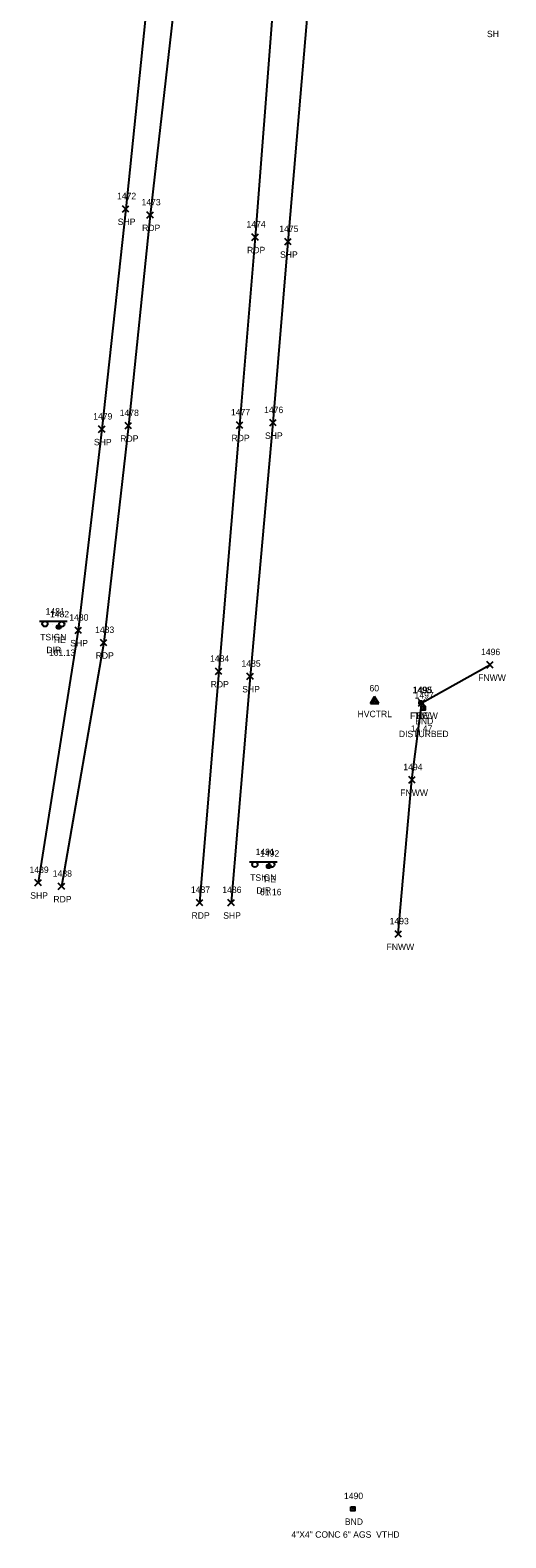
# Model space of a CAD drawing. Extents: x 1443960 to 1446865, y 610387 to 616706.
# Drawn here: x 1446513 to 1446660.7, y 610386.8 to 610855.3 of the extents above; entities that cross this region are included whole.
import ezdxf

# ---------------------------------------------------------------- set-up
doc = ezdxf.new("R2010")
doc.units = 0
for name, color, linetype in [('C_A', 7, 'Continuous'), ('C_C', 7, 'Continuous'), ('C_I', 7, 'Continuous'), ('CBP', 7, 'Continuous'), ('CPSM', 7, 'Continuous'), ('L_A', 7, 'Continuous'), ('L_I', 7, 'Continuous'), ('L_TIC', 7, 'Continuous'), ('LFNC', 7, 'Continuous'), ('M_A', 7, 'Continuous'), ('M_C', 7, 'Continuous'), ('M_I', 7, 'Continuous'), ('MHBP', 7, 'Continuous'), ('P_A', 7, 'Continuous'), ('P_I', 7, 'Continuous'), ('P_TIC', 7, 'Continuous'), ('PET', 7, 'Continuous'), ('PSP', 7, 'Continuous'), ('S_A', 7, 'Continuous'), ('S_C', 7, 'Continuous'), ('S_I', 7, 'Continuous'), ('SSGN', 7, 'Continuous')]:
    doc.layers.add(name, color=color, linetype=linetype)

msp = doc.modelspace()

# ---------------------------------------------------------------- linework, layer by layer
at = {"layer": 'CBP'}
for centre, radius in [((1446521.81, 610669.87), 0.625), ((1446521.81, 610669.87), 0.0833), ((1446634.4, 610646.3), 0.625), ((1446634.4, 610646.3), 0.0833), ((1446587.07, 610595.51), 0.625), ((1446587.07, 610595.51), 0.0833)]:
    msp.add_circle(centre, radius, dxfattribs=at)
at = {"layer": 'CPSM'}
for p, q in [((1446618.73, 610646.12), (1446619.98, 610648.28)), ((1446618.73, 610646.12), (1446619.98, 610646.84)), ((1446618.73, 610646.12), (1446621.23, 610646.12)), ((1446621.23, 610646.12), (1446619.98, 610648.28)), ((1446619.98, 610646.84), (1446619.98, 610648.28)), ((1446619.98, 610646.84), (1446619.98, 610646.84)), ((1446619.98, 610646.84), (1446621.23, 610646.12))]:
    msp.add_line(p, q, dxfattribs=at)
at = {"layer": 'L_TIC'}
for points in [[(1446654.78, 610657.12), (1446656.78, 610659.12)], [(1446656.78, 610657.12), (1446654.78, 610659.12)], [(1446633.64, 610645.31), (1446635.64, 610647.31)], [(1446635.64, 610645.31), (1446633.64, 610647.31)], [(1446630.58, 610621.37), (1446632.58, 610623.37)], [(1446632.58, 610621.37), (1446630.58, 610623.37)], [(1446626.32, 610573.48), (1446628.32, 610575.48)], [(1446628.32, 610573.48), (1446626.32, 610575.48)]]:
    msp.add_lwpolyline(points, dxfattribs=at)
at = {"layer": 'LFNC'}
msp.add_lwpolyline([(1446627.32, 610574.48), (1446631.58, 610622.37), (1446634.64, 610646.31), (1446655.78, 610658.12)], dxfattribs=at)
at = {"layer": 'MHBP'}
for points in [[(1446634.44, 610645.26), (1446635.69, 610645.26), (1446635.69, 610644.01), (1446634.44, 610644.01)], [(1446612.61, 610396.47), (1446613.86, 610396.47), (1446613.86, 610395.22), (1446612.61, 610395.22)]]:
    msp.add_lwpolyline(points, close=True, dxfattribs=at)
for centre in [(1446635.07, 610644.64), (1446613.24, 610395.85)]:
    msp.add_circle(centre, 0.0833, dxfattribs=at)
at = {"layer": 'P_TIC'}
for points in [[(1446541.65, 610798.79), (1446543.65, 610800.79)], [(1446543.65, 610798.79), (1446541.65, 610800.79)], [(1446549.26, 610796.89), (1446551.26, 610798.89)], [(1446551.26, 610796.89), (1446549.26, 610798.89)], [(1446581.86, 610790.01), (1446583.86, 610792.01)], [(1446583.86, 610790.01), (1446581.86, 610792.01)], [(1446592.05, 610788.59), (1446594.05, 610790.59)], [(1446594.05, 610788.59), (1446592.05, 610790.59)], [(1446587.39, 610732.33), (1446589.39, 610734.33)], [(1446589.39, 610732.33), (1446587.39, 610734.33)], [(1446534.25, 610730.33), (1446536.25, 610732.33)], [(1446536.25, 610730.33), (1446534.25, 610732.33)], [(1446542.48, 610731.42), (1446544.48, 610733.42)], [(1446544.48, 610731.42), (1446542.48, 610733.42)], [(1446577.03, 610731.6), (1446579.03, 610733.6)], [(1446579.03, 610731.6), (1446577.03, 610733.6)], [(1446526.9, 610667.85), (1446528.9, 610669.85)], [(1446528.9, 610667.85), (1446526.9, 610669.85)], [(1446534.83, 610664.01), (1446536.83, 610666.01)], [(1446536.83, 610664.01), (1446534.83, 610666.01)], [(1446570.55, 610655.07), (1446572.55, 610657.07)], [(1446572.55, 610655.07), (1446570.55, 610657.07)], [(1446580.3, 610653.53), (1446582.3, 610655.53)], [(1446582.3, 610653.53), (1446580.3, 610655.53)], [(1446514.47, 610589.43), (1446516.47, 610591.43)], [(1446516.47, 610589.43), (1446514.47, 610591.43)], [(1446521.7, 610588.27), (1446523.7, 610590.27)], [(1446523.7, 610588.27), (1446521.7, 610590.27)], [(1446564.6, 610583.23), (1446566.6, 610585.23)], [(1446566.6, 610583.23), (1446564.6, 610585.23)], [(1446574.41, 610583.21), (1446576.41, 610585.21)], [(1446576.41, 610583.21), (1446574.41, 610585.21)]]:
    msp.add_lwpolyline(points, dxfattribs=at)
at = {"layer": 'PET'}
for points in [[(1446586.96, 611148.93), (1446585.91, 611138.65), (1446581.07, 611085.82), (1446577.8, 611049), (1446573.67, 611008.09), (1446567.43, 610950.16), (1446562.94, 610911.75), (1446557.73, 610863.22), (1446550.26, 610797.89), (1446543.48, 610732.42), (1446535.83, 610665.01), (1446522.7, 610589.27)], [(1446610.71, 611136.75), (1446609.78, 611124.94), (1446606.08, 611083.4), (1446602.84, 611045.86), (1446594.91, 610952.22), (1446591.25, 610905.91), (1446588.27, 610860.89), (1446582.86, 610791.01), (1446578.03, 610732.6), (1446571.55, 610656.07), (1446565.6, 610584.23)]]:
    msp.add_lwpolyline(points, dxfattribs=at)
at = {"layer": 'PSP'}
for points in [[(1446576.92, 611154.08), (1446576.88, 611153.48), (1446576.38, 611146.03), (1446571.14, 611086.78), (1446567.69, 611049.79), (1446563.76, 611009.43), (1446561.38, 610989.08), (1446557.86, 610953.83), (1446553.98, 610913.79), (1446549.11, 610862.52), (1446542.65, 610799.79), (1446535.25, 610731.33), (1446527.9, 610668.85), (1446515.47, 610590.43)], [(1446619.04, 611132.42), (1446618.93, 611131.58), (1446619.27, 611123.52), (1446616.01, 611082.04), (1446613.23, 611044.06), (1446609.79, 611002.89), (1446606.09, 610951.91), (1446601.78, 610903.98), (1446599.17, 610861.23), (1446593.05, 610789.59), (1446588.39, 610733.33), (1446581.3, 610654.53), (1446575.41, 610584.21)]]:
    msp.add_lwpolyline(points, dxfattribs=at)
at = {"layer": 'SSGN'}
for p, q in [((1446515.89, 610671.65), (1446524.49, 610671.65)), ((1446519.91, 610670.75), (1446519.91, 610670.75)), ((1446581.12, 610596.92), (1446589.71, 610596.92)), ((1446585.14, 610596.02), (1446585.14, 610596.02))]:
    msp.add_line(p, q, dxfattribs=at)
for centre in [(1446517.55, 610670.82), (1446522.77, 610670.75), (1446582.78, 610596.09), (1446587.99, 610596.02)]:
    msp.add_circle(centre, 0.833, dxfattribs=at)

# ---------------------------------------------------------------- texts
at = {"layer": 'C_A'}
for s, p in [('TIE', (1446519.89, 610664.87)), ('HVCTRL', (1446614.67, 610641.84)), ('TIE', (1446632.48, 610641.3)), ('TIE', (1446585.15, 610590.51))]:
    msp.add_text(s, height=2, dxfattribs=at).set_placement(p)
at = {"layer": 'C_C'}
for s, p in [('101.13', (1446518.79, 610660.87)), ('14.47', (1446631.22, 610637.3)), ('61.16', (1446584.35, 610586.51))]:
    msp.add_text(s, height=2, dxfattribs=at).set_placement(p)
at = {"layer": 'C_I'}
for s, p in [('1482', (1446519.12, 610672.87)), ('60', (1446618.38, 610649.84)), ('1498', (1446631.71, 610649.3)), ('1492', (1446584.38, 610598.51))]:
    msp.add_text(s, height=2, dxfattribs=at).set_placement(p)
at = {"layer": 'L_A'}
for s, p in [('SH', (1446654.87, 610853.17)), ('FNWW', (1446652.13, 610653.12)), ('FNWW', (1446630.99, 610641.31)), ('FNWW', (1446627.93, 610617.37)), ('FNWW', (1446623.66, 610569.48))]:
    msp.add_text(s, height=2, dxfattribs=at).set_placement(p)
at = {"layer": 'L_I'}
for s, p in [('1496', (1446653.03, 610661.12)), ('1495', (1446631.95, 610649.31)), ('1494', (1446628.89, 610625.37)), ('1493', (1446624.63, 610577.48))]:
    msp.add_text(s, height=2, dxfattribs=at).set_placement(p)
at = {"layer": 'M_A'}
for p in [(1446632.56, 610639.64), (1446610.72, 610390.85)]:
    msp.add_text('BND', height=2, dxfattribs=at).set_placement(p)
at = {"layer": 'M_C'}
for s, p in [('DISTURBED', (1446627.5, 610635.64)), ('4"X4" CONC 6" AGS  VTHD', (1446594.11, 610386.85))]:
    msp.add_text(s, height=2, dxfattribs=at).set_placement(p)
at = {"layer": 'M_I'}
for s, p in [('1497', (1446632.37, 610647.64)), ('1490', (1446610.46, 610398.85))]:
    msp.add_text(s, height=2, dxfattribs=at).set_placement(p)
at = {"layer": 'P_A'}
for s, p in [('SHP', (1446540.18, 610794.79)), ('RDP', (1446547.75, 610792.89)), ('RDP', (1446580.35, 610786.01)), ('SHP', (1446590.59, 610784.59)), ('RDP', (1446540.97, 610727.42)), ('RDP', (1446575.52, 610727.6)), ('SHP', (1446585.92, 610728.33)), ('SHP', (1446532.78, 610726.33)), ('SHP', (1446525.43, 610663.85)), ('RDP', (1446533.32, 610660.01)), ('RDP', (1446569.04, 610651.07)), ('SHP', (1446578.84, 610649.53)), ('SHP', (1446513, 610585.43)), ('RDP', (1446520.18, 610584.27)), ('RDP', (1446563.09, 610579.23)), ('SHP', (1446572.94, 610579.21))]:
    msp.add_text(s, height=2, dxfattribs=at).set_placement(p)
at = {"layer": 'P_I'}
for s, p in [('1472', (1446539.95, 610802.79)), ('1473', (1446547.57, 610800.89)), ('1474', (1446580.17, 610794.01)), ('1475', (1446590.36, 610792.59)), ('1479', (1446532.55, 610734.33)), ('1478', (1446540.79, 610735.42)), ('1477', (1446575.34, 610735.6)), ('1476', (1446585.64, 610736.33)), ('1480', (1446525.12, 610671.85)), ('1483', (1446533.14, 610668.01)), ('1484', (1446568.85, 610659.07)), ('1485', (1446578.61, 610657.53)), ('1489', (1446512.77, 610593.43)), ('1488', (1446520, 610592.27)), ('1487', (1446562.91, 610587.23)), ('1486', (1446572.66, 610587.21))]:
    msp.add_text(s, height=2, dxfattribs=at).set_placement(p)
at = {"layer": 'S_A'}
for p in [(1446516.09, 610665.73), (1446581.31, 610591)]:
    msp.add_text('TSIGN', height=2, dxfattribs=at).set_placement(p)
at = {"layer": 'S_C'}
for p in [(1446518.01, 610661.73), (1446583.24, 610587)]:
    msp.add_text('DIR', height=2, dxfattribs=at).set_placement(p)
at = {"layer": 'S_I'}
for s, p in [('1481', (1446517.78, 610673.73)), ('1491', (1446583.01, 610599))]:
    msp.add_text(s, height=2, dxfattribs=at).set_placement(p)

doc.saveas('drawing.dxf')
